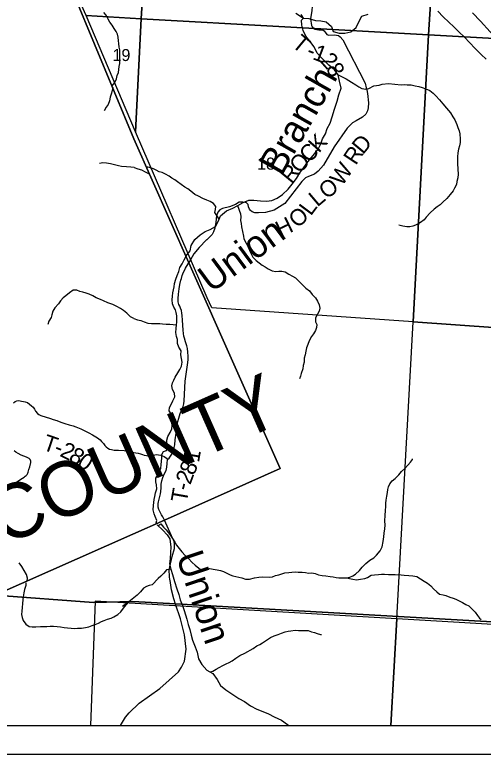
# Model space of a CAD drawing. Extents: x 0 to 44, y -23.8 to 22.
# Drawn here: x 3.933 to 5.562, y 14 to 16.572 of the extents above; entities that cross this region are included whole.
import ezdxf

# ---------------------------------------------------------------- set-up
doc = ezdxf.new("R2010")
doc.units = 0
for name, color, linetype in [('Default', 7, 'Continuous'), ('GM_X_County_Road', 7, 'Continuous'), ('GM_X_County_Text', 7, 'Continuous'), ('GM_X_Minor_River', 7, 'Continuous'), ('GM_X_Minor_River_Text', 7, 'Continuous'), ('GM_X_Section', 7, 'Continuous'), ('GM_X_Section_Text', 7, 'Continuous'), ('GM_X_State_Route', 7, 'Continuous'), ('GM_X_Township_Road', 7, 'Continuous'), ('GM_X_Township_Road_Text', 7, 'Continuous'), ('SH_Cut_Line', 7, 'Continuous'), ('SH_Data', 7, 'Continuous')]:
    doc.layers.add(name, color=color, linetype=linetype)

msp = doc.modelspace()

# ---------------------------------------------------------------- linework, layer by layer
at = {"layer": 'Default'}
for points in [[(2.3497, 20.9), (2.1, 20.9), (2.1, 14.1), (2.838, 14.1), (3.0317, 14.1856), (3.8639, 14.5533), (4.3443, 14.7655), (4.4538, 14.8144), (4.856, 14.9939), (4.5387, 15.7097), (4.3476, 16.1408), (4.1422, 16.6361), (4.026, 16.9163), (3.7907, 17.4383), (3.763, 17.5087), (3.455, 18.29), (3.1789, 18.9421), (3.1321, 19.0527), (3.0496, 19.2474), (3.0092, 19.3427), (2.8013, 19.8369), (2.472, 20.6113)], [(2.838, 14.1), (7.2659, 14.1), (7.2787, 14.3616), (7.2065, 14.3659), (6.267, 14.4223), (4.4919, 14.5227), (4.3437, 14.5311), (4.2071, 14.5278), (3.8639, 14.5533), (3.0317, 14.1856)], [(4.1965, 14.1), (5.2407, 14.1), (5.2616, 14.4705), (4.2129, 14.5323)], [(5.2407, 14.1), (6.2484, 14.1), (6.2643, 14.4116), (5.2616, 14.4705)]]:
    msp.add_lwpolyline(points, close=True, dxfattribs=at)
msp.add_lwpolyline([(4.1422, 16.6361), (4.3476, 16.1408), (4.5387, 15.7097), (4.856, 14.9939), (4.4538, 14.8144), (4.3443, 14.7655), (3.8639, 14.5533), (4.2071, 14.5278), (4.3437, 14.5311), (4.4919, 14.5227), (6.267, 14.4223), (7.2065, 14.3659), (7.2787, 14.3616), (7.5613, 14.343)], dxfattribs=at)
at = {"layer": 'GM_X_County_Road'}
for points in [[(4.4731, 14.6064), (4.4713, 14.6182), (4.4705, 14.6409), (4.4807, 14.6875), (4.4885, 14.7156), (4.4892, 14.7216), (4.4893, 14.7319), (4.4871, 14.7393), (4.4826, 14.7487), (4.454, 14.8139)], [(4.3016, 14.1), (4.3182, 14.1283), (4.3314, 14.1444), (4.3654, 14.1771), (4.4378, 14.2288), (4.5023, 14.2871), (4.5135, 14.3025), (4.5237, 14.3236), (4.5289, 14.3656), (4.5239, 14.4147), (4.5096, 14.4711), (4.4922, 14.5222), (4.486, 14.5401), (4.4786, 14.5721), (4.4735, 14.6044), (4.4731, 14.6064)]]:
    msp.add_lwpolyline(points, dxfattribs=at)
at = {"layer": 'GM_X_Minor_River'}
for points in [[(4.272, 16.3251), (4.2818, 16.3365), (4.2868, 16.3486), (4.2895, 16.3611), (4.2945, 16.3717), (4.2957, 16.3812), (4.2965, 16.3926), (4.2992, 16.4021), (4.2985, 16.4153), (4.2982, 16.4286), (4.299, 16.4389), (4.2987, 16.4495), (4.2965, 16.4597), (4.2958, 16.4715), (4.2943, 16.4817), (4.2932, 16.4946), (4.2902, 16.5041), (4.2858, 16.514), (4.279, 16.5243), (4.2726, 16.5353), (4.2644, 16.546), (4.2584, 16.5566), (4.2509, 16.5703), (4.2426, 16.5802)], [(4.9109, 16.5773), (4.9377, 16.5598), (4.9559, 16.5586), (4.979, 16.5518), (4.9975, 16.5506), (5.0165, 16.5472), (5.0346, 16.5316), (5.041, 16.5133), (5.0618, 16.5083), (5.0815, 16.5083), (5.1019, 16.5121), (5.1209, 16.528), (5.1304, 16.5493), (5.1407, 16.5676), (5.1623, 16.574)], [(4.9377, 16.5598), (4.9289, 16.5726)], [(5.4046, 16.5848), (5.4231, 16.5646), (5.4427, 16.546), (5.4601, 16.5304), (5.4774, 16.5129), (5.4971, 16.4938), (5.5148, 16.4756), (5.5345, 16.4546), (5.5549, 16.4333), (5.5726, 16.417)], [(4.5291, 15.7331), (4.5429, 15.7506), (4.5464, 15.7696), (4.5601, 15.7898), (4.5779, 15.8069), (4.5957, 15.8179), (4.6128, 15.8251), (4.631, 15.8357), (4.642, 15.8547), (4.6492, 15.873), (4.6701, 15.8901), (4.6913, 15.8988), (4.7087, 15.9083), (4.7281, 15.9185), (4.747, 15.9269), (4.7652, 15.9268), (4.7875, 15.9249), (4.8083, 15.9241), (4.8269, 15.9264), (4.8462, 15.934), (4.864, 15.9469), (4.8838, 15.9651), (4.8982, 15.983), (4.9134, 16.0024), (4.9244, 16.0221), (4.9384, 16.0408), (4.9521, 16.0609), (4.9715, 16.0825), (4.9886, 16.1046), (4.9973, 16.1232), (5.003, 16.1407), (5.0144, 16.1578), (5.0201, 16.1768), (5.0304, 16.1954), (5.0373, 16.2171), (5.0457, 16.2437), (5.0544, 16.2718), (5.0598, 16.2939), (5.0678, 16.3171), (5.0622, 16.3414), (5.058, 16.3635), (5.0456, 16.381), (5.0256, 16.3966), (5.0025, 16.4198), (4.9852, 16.4388), (4.9739, 16.4609), (4.9595, 16.4799), (4.9452, 16.497), (4.9358, 16.5176), (4.932, 16.5358), (4.9305, 16.5529), (4.9377, 16.5598)], [(5.058, 16.3635), (5.0861, 16.3489), (5.1039, 16.3379), (5.1194, 16.3277), (5.13, 16.3212), (5.1406, 16.3155), (5.1546, 16.3133), (5.1648, 16.3159), (5.1825, 16.3247), (5.2007, 16.3273), (5.2113, 16.3308), (5.2332, 16.3327), (5.2774, 16.3278), (5.2872, 16.3289), (5.2974, 16.3285), (5.3114, 16.3278), (5.3258, 16.3251), (5.3379, 16.3228), (5.35, 16.3194), (5.3628, 16.3149), (5.3761, 16.3088), (5.3885, 16.2997), (5.398, 16.2903), (5.4101, 16.2766), (5.4222, 16.2626), (5.435, 16.2467), (5.4486, 16.2304), (5.4566, 16.2167), (5.4641, 16.2065), (5.4709, 16.1902), (5.4743, 16.1799), (5.4792, 16.1678), (5.4815, 16.158), (5.4826, 16.1394), (5.4819, 16.128), (5.48, 16.1166), (5.4769, 16.1049), (5.4743, 16.0923), (5.4732, 16.0783), (5.4732, 16.0544), (5.4739, 16.0347), (5.475, 16.0173), (5.4739, 16.0047), (5.4709, 15.9915), (5.469, 15.9816), (5.4622, 15.9687), (5.4576, 15.9592), (5.4474, 15.9463), (5.4357, 15.933), (5.4221, 15.9198), (5.4123, 15.9114), (5.4021, 15.9034), (5.3922, 15.8955), (5.3782, 15.8833), (5.3643, 15.8678), (5.3567, 15.8583), (5.3442, 15.8499), (5.3321, 15.842), (5.3174, 15.8367), (5.3068, 15.8344), (5.2966, 15.834), (5.2822, 15.837), (5.2686, 15.8397)], [(4.2745, 16.3191), (4.2732, 16.3145), (4.2697, 16.2991), (4.2654, 16.2851), (4.2623, 16.2722), (4.2585, 16.2601), (4.2516, 16.2503), (4.244, 16.2378)], [(4.3488, 16.0407), (4.3373, 16.0416), (4.3218, 16.0435), (4.304, 16.0444), (4.2942, 16.0464), (4.2802, 16.0499), (4.2659, 16.0537), (4.2523, 16.0553), (4.2402, 16.0569), (4.2281, 16.0551)], [(4.3488, 16.0407), (4.3616, 16.0357), (4.3737, 16.0326), (4.3873, 16.0261), (4.4005, 16.0192), (4.403, 16.0176)], [(4.6444, 15.8607), (4.6356, 15.8734), (4.6292, 15.8837), (4.6319, 15.8943), (4.6327, 15.9049), (4.624, 15.9152), (4.6127, 15.9224), (4.601, 15.9266), (4.5874, 15.9331), (4.5726, 15.9408), (4.5601, 15.9473), (4.5454, 15.9579), (4.5348, 15.966), (4.525, 15.9728), (4.5125, 15.982), (4.4993, 15.9904), (4.4895, 15.9976), (4.4797, 16.0033), (4.4699, 16.0106), (4.4578, 16.0178), (4.4464, 16.0235), (4.4355, 16.0259), (4.4256, 16.0312), (4.4154, 16.0362), (4.4056, 16.0396), (4.3958, 16.0423), (4.3939, 16.0423)], [(4.7084, 15.9081), (4.7185, 15.8792), (4.7189, 15.8686), (4.7185, 15.8568), (4.7204, 15.8458), (4.7222, 15.8344), (4.7252, 15.8185), (4.7293, 15.8022), (4.7304, 15.7927), (4.7383, 15.7771), (4.7459, 15.763), (4.7511, 15.7501), (4.7564, 15.7387), (4.7617, 15.7285), (4.773, 15.7167), (4.7836, 15.7087), (4.7934, 15.7014), (4.8044, 15.6953), (4.8142, 15.6885), (4.8282, 15.6816), (4.841, 15.6789), (4.8513, 15.68), (4.8618, 15.6803), (4.874, 15.6776), (4.886, 15.67), (4.8989, 15.6624), (4.9099, 15.6566), (4.9204, 15.6467), (4.9287, 15.6368), (4.9453, 15.6209), (4.9582, 15.6113), (4.9672, 15.5995), (4.9789, 15.587), (4.9861, 15.576), (4.9921, 15.563), (4.9936, 15.552), (4.9913, 15.5407), (4.9864, 15.5301), (4.9791, 15.5176), (4.9787, 15.5039), (4.984, 15.4941), (4.9828, 15.4838), (4.9786, 15.4736), (4.9718, 15.4626), (4.9657, 15.4528), (4.9574, 15.438), (4.9528, 15.4251), (4.9482, 15.4138), (4.9452, 15.402), (4.9428, 15.3892), (4.9398, 15.377), (4.9398, 15.3641), (4.9367, 15.3524), (4.9355, 15.341), (4.9298, 15.324), (4.9271, 15.3145), (4.9237, 15.3058)], [(4.4235, 14.8), (4.4273, 14.8125), (4.4221, 14.8266), (4.4176, 14.8364), (4.4143, 14.8497), (4.4155, 14.8653), (4.4171, 14.8755), (4.4179, 14.8858), (4.4199, 14.8967), (4.4226, 14.9092), (4.4269, 14.9236), (4.4266, 14.9365), (4.4244, 14.9475), (4.4244, 14.9604), (4.4306, 14.9722), (4.4359, 14.9824), (4.4413, 14.9948), (4.4421, 15.007), (4.4441, 15.0191), (4.4453, 15.0293), (4.4442, 15.0426), (4.45, 15.0528), (4.4606, 15.0562), (4.4652, 15.0671), (4.4619, 15.0816), (4.4623, 15.0918), (4.4662, 15.1047), (4.4734, 15.1194), (4.4799, 15.1315), (4.4808, 15.1437), (4.479, 15.1543), (4.4775, 15.1687), (4.4784, 15.1812), (4.4705, 15.1938), (4.4709, 15.2055), (4.4774, 15.2161), (4.4836, 15.2297), (4.4905, 15.2426), (4.489, 15.2559), (4.4815, 15.2684), (4.4797, 15.2813), (4.4817, 15.2912), (4.4863, 15.301), (4.4916, 15.3112), (4.5008, 15.326), (4.5069, 15.3381), (4.5131, 15.3498), (4.5158, 15.3638), (4.5132, 15.3763), (4.511, 15.3896), (4.5115, 15.4033), (4.5036, 15.4158), (4.4988, 15.4288), (4.4989, 15.4424), (4.4963, 15.4527), (4.4937, 15.4663), (4.4942, 15.4808), (4.4954, 15.4936), (4.497, 15.5031), (4.4974, 15.5126), (4.4964, 15.5251), (4.4949, 15.5361), (4.4919, 15.5456), (4.4867, 15.5555), (4.4819, 15.5665), (4.4808, 15.5802), (4.4817, 15.5935), (4.4829, 15.6052), (4.4848, 15.6151), (4.4872, 15.6261), (4.4891, 15.6378), (4.493, 15.6518), (4.498, 15.6651), (4.5034, 15.6787), (4.5076, 15.6927), (4.5156, 15.7059), (4.5229, 15.7191), (4.5292, 15.7328)], [(4.3473, 15.5154), (4.336, 15.5216), (4.3228, 15.5338), (4.3115, 15.543), (4.3006, 15.5499), (4.2882, 15.5571), (4.2746, 15.5637), (4.2569, 15.5695), (4.2418, 15.5771), (4.232, 15.5817), (4.2169, 15.5875), (4.2052, 15.594), (4.1924, 15.6006), (4.1818, 15.604), (4.1701, 15.6068), (4.1599, 15.6099), (4.1494, 15.6141), (4.1361, 15.6146), (4.124, 15.6052), (4.1114, 15.5946), (4.1015, 15.5871), (4.0928, 15.5773), (4.0855, 15.5671), (4.073, 15.5524), (4.0661, 15.541), (4.0626, 15.5285), (4.0595, 15.5187), (4.0523, 15.5062), (4.048, 15.4941)], [(4.3473, 15.5154), (4.3598, 15.5108), (4.3719, 15.5081), (4.3839, 15.5035), (4.3964, 15.4992), (4.4092, 15.4976), (4.424, 15.4983), (4.4376, 15.4978), (4.4474, 15.4974), (4.4603, 15.4954), (4.4728, 15.4961), (4.4954, 15.4938)], [(4.4314, 14.7949), (4.441, 14.8013), (4.4505, 14.7902), (4.4595, 14.78), (4.4682, 14.7697), (4.4754, 14.7602), (4.4814, 14.7507), (4.4897, 14.7378), (4.4961, 14.7271), (4.5048, 14.7157), (4.5146, 14.7039), (4.5259, 14.6917), (4.538, 14.6803), (4.5504, 14.6674), (4.5603, 14.6575), (4.5731, 14.6476), (4.5859, 14.6377), (4.5992, 14.6422), (4.6117, 14.6455), (4.6234, 14.644), (4.6367, 14.6417), (4.6484, 14.6393), (4.6594, 14.6359), (4.6707, 14.6294), (4.682, 14.624), (4.6919, 14.6206), (4.713, 14.616), (4.7233, 14.6133), (4.7357, 14.6094), (4.7497, 14.609), (4.7668, 14.6131), (4.7815, 14.6161), (4.7944, 14.6164), (4.8186, 14.6163), (4.8292, 14.6171), (4.8398, 14.6212), (4.8516, 14.6238), (4.8626, 14.6272), (4.8724, 14.6309), (4.886, 14.6316), (4.8966, 14.6335), (4.9084, 14.6338), (4.9186, 14.6334), (4.933, 14.633), (4.9447, 14.6318), (4.9549, 14.6299), (4.9666, 14.6306), (4.9776, 14.6283), (4.9893, 14.6244), (5.0026, 14.6221), (5.0147, 14.6202), (5.0302, 14.6186), (5.0404, 14.617), (5.0506, 14.6143), (5.0605, 14.6132), (5.0741, 14.6135), (5.087, 14.6135), (5.0987, 14.6161), (5.1085, 14.6206), (5.1184, 14.6266), (5.1321, 14.6395), (5.1419, 14.6508), (5.1544, 14.6636), (5.1677, 14.6754), (5.1817, 14.6829), (5.1908, 14.6927), (5.2041, 14.7071), (5.2106, 14.7218), (5.2148, 14.7397), (5.2171, 14.7556), (5.2183, 14.7688), (5.2202, 14.7836), (5.221, 14.7969), (5.2207, 14.8113), (5.2211, 14.8299), (5.2227, 14.8477), (5.2234, 14.8614), (5.2242, 14.8727), (5.2254, 14.8837), (5.2266, 14.8974), (5.2289, 14.9106), (5.2304, 14.9205), (5.2327, 14.93), (5.2377, 14.941), (5.2456, 14.9508), (5.2559, 14.9591), (5.2688, 14.9712), (5.2786, 14.9829), (5.2893, 14.9939), (5.3006, 15.0048), (5.309, 15.0158), (5.3162, 15.0256), (5.3166, 15.0271)], [(4.4281, 14.798), (4.4484, 14.7794), (4.463, 14.7634), (4.4721, 14.7495), (4.4766, 14.7206), (4.475, 14.7012), (4.4742, 14.6807), (4.4715, 14.6621), (4.476, 14.6442), (4.4813, 14.6256), (4.4884, 14.6005), (4.4967, 14.5757), (4.5035, 14.556), (4.5083, 14.5373), (4.5162, 14.5168), (4.5223, 14.4997), (4.5313, 14.47), (4.5365, 14.4514), (4.5426, 14.4339), (4.5471, 14.4145), (4.5519, 14.3966), (4.5602, 14.373), (4.5681, 14.3544), (4.5726, 14.3319), (4.5839, 14.3118), (4.6017, 14.2923), (4.6221, 14.2809), (4.6368, 14.2596), (4.6492, 14.2391), (4.6674, 14.2234), (4.6912, 14.2075), (4.7123, 14.1941), (4.7328, 14.1835), (4.7535, 14.1678), (4.7747, 14.1572), (4.7959, 14.1488), (4.8159, 14.1408), (4.8352, 14.1297), (4.8606, 14.1183), (4.8817, 14.1031), (4.8868, 14.1)], [(3.9768, 14.6023), (3.9776, 14.6127), (3.9742, 14.6256), (3.966, 14.639), (3.9585, 14.6534), (3.9492, 14.6656)], [(4.476, 14.6442), (4.4607, 14.6412), (4.4523, 14.6298), (4.4417, 14.6189), (4.4318, 14.6113), (4.4114, 14.5886), (4.4004, 14.5868), (4.3909, 14.583), (4.3814, 14.577), (4.3704, 14.5653), (4.3594, 14.5532), (4.3304, 14.5302), (4.3302, 14.532)], [(5.0874, 14.6136), (5.0979, 14.6108), (5.1089, 14.6084), (5.1218, 14.6069), (5.1354, 14.6083), (5.1501, 14.6106), (5.1604, 14.6151), (5.1729, 14.6222), (5.1839, 14.6241), (5.1982, 14.6256), (5.2081, 14.6263), (5.2191, 14.6259), (5.2331, 14.6247), (5.2444, 14.6246), (5.2558, 14.625), (5.277, 14.6238), (5.2879, 14.6226), (5.3031, 14.6214), (5.3174, 14.6206), (5.3318, 14.6179), (5.3447, 14.6102), (5.3571, 14.6015), (5.3689, 14.595), (5.3798, 14.5862), (5.3892, 14.5752), (5.4009, 14.5653), (5.4108, 14.5569), (5.4225, 14.5542), (5.4323, 14.5519), (5.4459, 14.5461), (5.4573, 14.5423), (5.4675, 14.5389), (5.4788, 14.5335), (5.4905, 14.5274), (5.5015, 14.5209), (5.5125, 14.5156), (5.523, 14.5053), (5.5347, 14.4935), (5.5427, 14.4828), (5.5498, 14.4733), (5.5547, 14.4691)], [(3.9724, 14.5962), (3.9716, 14.5863), (3.9678, 14.573), (3.9651, 14.5613), (3.9624, 14.5476), (3.9609, 14.5374), (3.9601, 14.5241), (3.9593, 14.5105), (3.9577, 14.498), (3.9569, 14.4862), (3.9592, 14.4756), (3.9625, 14.4653), (3.9719, 14.4524), (3.9836, 14.4444), (3.9935, 14.4428), (4.0067, 14.4436), (4.0234, 14.4439), (4.0332, 14.4439), (4.0445, 14.4446), (4.057, 14.4457), (4.0676, 14.4453), (4.0808, 14.4437), (4.0926, 14.4433), (4.105, 14.4406), (4.1168, 14.4394), (4.1292, 14.4379), (4.1402, 14.4375), (4.1512, 14.4382), (4.1656, 14.4389), (4.1799, 14.4404), (4.1909, 14.4434), (4.2027, 14.4472), (4.2133, 14.4513), (4.2242, 14.4562), (4.2352, 14.4615), (4.2447, 14.4656), (4.2553, 14.4694), (4.2682, 14.4731), (4.278, 14.4777), (4.2921, 14.4856), (4.3023, 14.4954), (4.3114, 14.5079), (4.3205, 14.52), (4.3304, 14.5302), (4.3084, 14.514)], [(4.6117, 14.2867), (4.6221, 14.2886), (4.6339, 14.2958), (4.6437, 14.3018), (4.6566, 14.309), (4.6688, 14.3146), (4.6786, 14.3188), (4.6892, 14.3252), (4.7021, 14.3338), (4.7161, 14.3433), (4.7332, 14.3519), (4.7627, 14.3677), (4.7753, 14.3764), (4.7855, 14.3821), (4.795, 14.3877), (4.809, 14.3972), (4.8226, 14.4058), (4.8351, 14.4119), (4.8488, 14.4164), (4.8609, 14.4205), (4.8734, 14.4254), (4.884, 14.4276), (4.8938, 14.4295), (4.9079, 14.4317), (4.9196, 14.4301), (4.9306, 14.4301), (4.9438, 14.4304), (4.9536, 14.43), (4.965, 14.4262), (4.9756, 14.4239), (4.9854, 14.4196), (4.9968, 14.4166), (4.9994, 14.4162)]]:
    msp.add_lwpolyline(points, dxfattribs=at)
at = {"layer": 'GM_X_Section'}
for points in [[(3.7148, 17.6484), (4.437, 17.5902), (4.3733, 16.5584), (4.182, 16.5693), (4.0894, 16.7757), (3.8788, 17.2584)], [(4.437, 17.5902), (5.4377, 17.5257), (5.3718, 16.5024), (4.3733, 16.5584)], [(5.4377, 17.5257), (6.4419, 17.4633), (6.3745, 16.447), (5.3718, 16.5024)], [(4.182, 16.5693), (4.3733, 16.5584), (4.3537, 16.1645)], [(4.3733, 16.5584), (5.3718, 16.5024), (5.3182, 15.5035), (4.6181, 15.5526), (4.6026, 15.5875), (4.3537, 16.1645)], [(5.3718, 16.5024), (6.3745, 16.447), (6.3163, 15.4337), (5.3182, 15.5035)], [(6.3163, 15.4337), (6.2643, 14.4116), (5.2616, 14.4705), (5.3182, 15.5035)]]:
    msp.add_lwpolyline(points, close=True, dxfattribs=at)
at = {"layer": 'GM_X_State_Route'}
msp.add_lwpolyline([(5.6198, 16.4752), (5.553, 16.55), (5.5249, 16.5786)], dxfattribs=at)
at = {"layer": 'GM_X_Township_Road'}
for points in [[(4.9774, 16.6512), (4.9696, 16.6259), (4.9667, 16.6184), (4.9678, 16.6004), (4.9667, 16.5864), (4.9618, 16.5574), (4.9657, 16.5347), (4.9672, 16.5303), (4.9718, 16.5246), (4.9764, 16.5218), (4.9902, 16.52), (5.0035, 16.52), (5.006, 16.5184), (5.0087, 16.5161), (5.018, 16.5035), (5.0251, 16.5006), (5.0456, 16.5019), (5.0587, 16.4997), (5.0644, 16.4955), (5.0744, 16.4847), (5.1523, 16.334), (5.1557, 16.3183)], [(5.1557, 16.3183), (5.1574, 16.3105), (5.1601, 16.2978), (5.1638, 16.2659), (5.1624, 16.2481), (5.16, 16.2378), (5.1541, 16.2262), (5.1422, 16.2161), (5.1204, 16.2028), (5.1082, 16.1961), (5.0894, 16.177), (5.0445, 16.1132), (5.0071, 16.0488), (4.9886, 16.0282), (4.9756, 16.0178), (4.955, 16.009), (4.9443, 16.0049), (4.9313, 15.9918), (4.8726, 15.916), (4.8355, 15.8927), (4.8058, 15.8844), (4.7804, 15.8825), (4.7679, 15.8834), (4.7592, 15.8862), (4.7529, 15.8912), (4.7491, 15.8962), (4.7458, 15.9039), (4.7445, 15.9119), (4.7392, 15.9176), (4.7264, 15.9201), (4.7139, 15.9199), (4.7005, 15.9118), (4.6796, 15.9045), (4.656, 15.8987), (4.6464, 15.8936), (4.6395, 15.8853), (4.6351, 15.8721), (4.6322, 15.8501), (4.6296, 15.8293), (4.6245, 15.8165), (4.6198, 15.8082), (4.6014, 15.7896), (4.6006, 15.7889)], [(4.6006, 15.7889), (4.5744, 15.7625), (4.5566, 15.74), (4.5389, 15.7092)], [(4.454, 14.8139), (4.4487, 14.8255), (4.4439, 14.8331), (4.4378, 14.8439), (4.4338, 14.8515), (4.4321, 14.8588), (4.4315, 14.8649), (4.4319, 14.872), (4.4333, 14.8782), (4.4354, 14.8867), (4.4374, 14.8962), (4.44, 14.9057), (4.4416, 14.9136), (4.4426, 14.9271), (4.4429, 14.9391), (4.4449, 14.9506), (4.4483, 14.9619), (4.4546, 14.9765), (4.4594, 14.9874), (4.4621, 14.9983), (4.4637, 15.0112), (4.4649, 15.0256), (4.4697, 15.0292), (4.4724, 15.0327), (4.4794, 15.0436), (4.4835, 15.0539), (4.4865, 15.0624), (4.4897, 15.0761), (4.4914, 15.0937), (4.4948, 15.117), (4.4982, 15.1444), (4.5005, 15.1568), (4.5035, 15.1687), (4.5087, 15.1855), (4.5156, 15.2014), (4.5184, 15.2093), (4.5211, 15.2192), (4.5223, 15.2291), (4.5263, 15.2979), (4.5306, 15.3298), (4.5344, 15.3539), (4.5362, 15.3712), (4.5364, 15.384), (4.5356, 15.3985), (4.5338, 15.4117), (4.5322, 15.4206), (4.5275, 15.4339), (4.5235, 15.4472), (4.5213, 15.4535), (4.5203, 15.4634), (4.5191, 15.4755), (4.517, 15.5103), (4.516, 15.5259), (4.5148, 15.5342), (4.5128, 15.5431), (4.5098, 15.5515), (4.5069, 15.558), (4.5041, 15.5647), (4.5019, 15.5738), (4.5011, 15.5849), (4.5025, 15.6005), (4.5053, 15.6187), (4.5075, 15.6338), (4.5112, 15.649), (4.5126, 15.6552), (4.5158, 15.6652), (4.5199, 15.6767), (4.5243, 15.6852), (4.5271, 15.6908), (4.53, 15.6961), (4.5389, 15.7092)], [(3.9288, 15.2221), (3.9353, 15.2263), (3.9411, 15.2287), (3.9466, 15.2304), (3.9523, 15.2297), (3.9573, 15.2285), (3.9636, 15.2263), (3.9694, 15.2251), (3.9771, 15.2231), (3.9852, 15.2176), (3.9919, 15.2122), (3.9971, 15.2071), (4.0016, 15.2004), (4.006, 15.1936), (4.0123, 15.1851), (4.0176, 15.1814), (4.024, 15.1778), (4.0579, 15.1674), (4.0671, 15.1643), (4.0798, 15.1602), (4.0938, 15.1552), (4.1075, 15.1503), (4.1227, 15.1457), (4.137, 15.142), (4.1457, 15.1386), (4.1633, 15.1319), (4.1776, 15.1244), (4.1912, 15.118), (4.2033, 15.1109), (4.2205, 15.101), (4.2298, 15.0935), (4.2355, 15.0876), (4.2415, 15.0806), (4.2468, 15.0737), (4.2512, 15.0696), (4.2565, 15.0646), (4.2627, 15.0616), (4.2694, 15.0597), (4.2787, 15.0579), (4.2939, 15.0571), (4.3143, 15.0561), (4.323, 15.0547), (4.3311, 15.0533), (4.3371, 15.0515), (4.3476, 15.0496), (4.3547, 15.0488), (4.362, 15.0474), (4.3709, 15.0448), (4.3772, 15.0426), (4.3838, 15.0407), (4.3909, 15.0385), (4.3964, 15.0373), (4.4022, 15.0371), (4.4081, 15.0381), (4.4133, 15.0399), (4.4202, 15.0418), (4.4269, 15.0422), (4.4329, 15.0418), (4.4412, 15.0397), (4.4524, 15.0353), (4.4614, 15.0302), (4.4649, 15.0256)], [(3.9213, 14.9338), (3.9548, 14.9565), (3.9664, 14.9641), (3.9692, 14.9668), (3.9729, 14.97), (3.9765, 14.9733), (3.9783, 14.9771), (3.9797, 14.9813), (3.982, 14.9898), (3.9858, 14.9999), (3.989, 15.0141), (3.9893, 15.0191), (3.9874, 15.0246), (3.983, 15.0288), (3.9743, 15.0333), (3.9559, 15.0405), (3.9452, 15.0454), (3.9371, 15.0506), (3.9314, 15.0555)]]:
    msp.add_lwpolyline(points, dxfattribs=at)
at = {"layer": 'SH_Cut_Line'}
for points in [[(2.1, 20.9), (2.1, 14.1), (2.838, 14.1), (3.0317, 14.1856), (3.8639, 14.5533), (4.3443, 14.7655), (4.4538, 14.8144), (4.856, 14.9939), (4.5387, 15.7097), (4.3476, 16.1408), (4.1422, 16.6361)], [(4.1422, 16.6361), (4.3476, 16.1408), (4.5387, 15.7097), (4.856, 14.9939), (4.4538, 14.8144), (4.3443, 14.7655), (3.8639, 14.5533), (3.0317, 14.1856), (2.838, 14.1), (8.9, 14.1)]]:
    msp.add_lwpolyline(points, dxfattribs=at)
at = {"layer": 'SH_Data'}
for p, q in [((2.1, 14.1), (8.9, 14.1)), ((2, 14), (9, 14))]:
    msp.add_line(p, q, dxfattribs=at)

# ---------------------------------------------------------------- texts
at = {"layer": 'GM_X_County_Text'}
msp.add_text('SCIOTO COUNTY', height=0.189394, rotation=23.8999, dxfattribs=at).set_placement((2.9443, 14.3021))
at = {"layer": 'GM_X_Minor_River_Text'}
for s, height, rotation, p in [('Branch', 0.09468, 60.4883, (4.861, 16.0074)), ('Union', 0.09469, 36.4864, (4.6163, 15.6022)), ('Union', 0.09469, 288.4935, (4.4936, 14.689))]:
    msp.add_text(s, height=height, rotation=rotation, dxfattribs=at).set_placement(p)
at = {"layer": 'GM_X_Section_Text'}
for s, p in [('19', (4.2731, 16.411)), ('18', (4.776, 16.0335))]:
    msp.add_text(s, height=0.04186, rotation=0, dxfattribs=at).set_placement(p)
at = {"layer": 'GM_X_Township_Road_Text'}
for s, rotation, p in [('T', 320.2954, (4.8938, 16.4642)), ('1', 338.9616, (4.9659, 16.4185)), ('-', 339.3316, (4.9442, 16.4267)), ('2', 311.7048, (4.9928, 16.41)), ('8', 297.5659, (5.014, 16.3869)), ('K', 48.5404, (4.9909, 16.0889)), ('D', 50.3178, (5.1442, 16.0836)), ('C', 47.0413, (4.958, 16.0536)), ('R', 56.5719, (5.1194, 16.046)), ('O', 47.3872, (4.9242, 16.0168)), ('R', 50.7166, (4.8952, 15.9814)), ('W', 55.7065, (5.0716, 15.9731)), ('O', 36.8342, (5.0175, 15.9284)), ('L', 40.182, (4.9857, 15.9016)), ('O', 41.2422, (4.9162, 15.8275)), ('L', 53.2926, (4.9627, 15.87)), ('H', 25.915, (4.8575, 15.7965)), ('T', 341.1029, (4.0268, 15.06)), ('2', 333.8818, (4.087, 15.0385)), ('-', 338.6226, (4.0664, 15.0465)), ('8', 328.8662, (4.1173, 15.0237)), ('0', 325.3162, (4.1465, 15.0061)), ('1', 80.0746, (4.5737, 15.0129)), ('8', 66.6039, (4.5556, 14.9669)), ('2', 69.7266, (4.5438, 14.9348)), ('T', 79.9631, (4.5314, 14.8729)), ('-', 75.8606, (4.5386, 14.9137))]:
    msp.add_text(s, height=0.0568, rotation=rotation, dxfattribs=at).set_placement(p)

doc.saveas('drawing.dxf')
